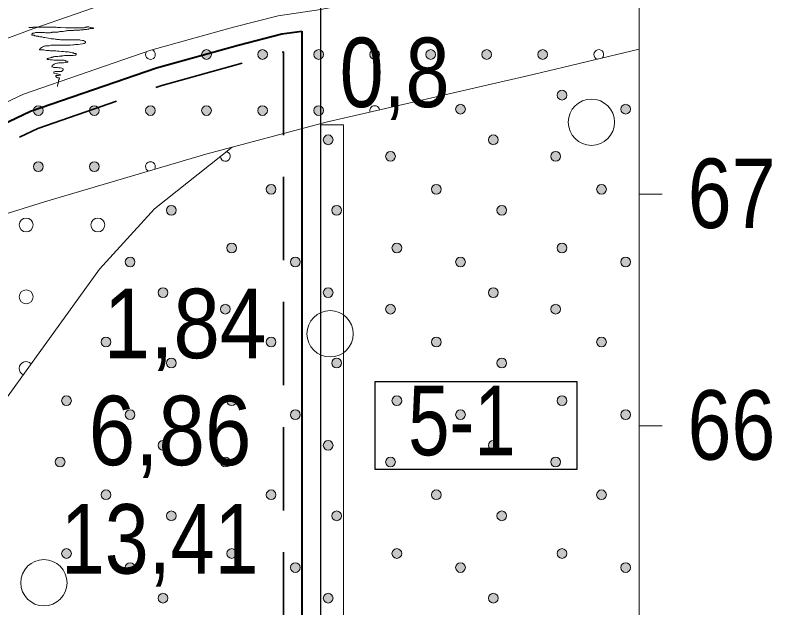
# Model space of a CAD drawing. Extents: x 640104 to 640970, y 6442278 to 6442689.
# Drawn here: x 640391.47 to 640424.15, y 6442590.14 to 6442615.73 of the extents above; entities that cross this region are included whole.
import ezdxf
from ezdxf.enums import TextEntityAlignment as Align

# ---------------------------------------------------------------- set-up
doc = ezdxf.new("R2010")
doc.units = 0
doc.header["$LTSCALE"] = 1.2
doc.linetypes.add('MEDIUM_DASHED', pattern=[4.5, 3, -1.5])
for name, color, linetype, lineweight in [('30', 7, 'Continuous', 13), ('31', 7, 'Continuous', 13), ('32', 7, 'Continuous', 25), ('33', 7, 'Continuous', 13), ('35', 7, 'Continuous', 35), ('40', 7, 'Continuous', 13), ('43', 7, 'Continuous', 13), ('44', 7, 'Continuous', 13), ('45', 7, 'Continuous', 13), ('47', 7, 'Continuous', 13)]:
    doc.layers.add(name, color=color, linetype=linetype, lineweight=lineweight)

msp = doc.modelspace()

# ---------------------------------------------------------------- hatches: boundary and pattern name
at = {"layer": '44'}
for points in [[(640415.301, 6442612.277, 1), (640414.881, 6442612.277, 1)], [(640410.916, 6442611.671, 1), (640410.496, 6442611.671, 1)], [(640418.049, 6442611.671, 1), (640417.629, 6442611.671, 1)], [(640405.202, 6442610.349, 1), (640404.782, 6442610.349, 1)], [(640412.335, 6442610.349, 1), (640411.915, 6442610.349, 1)], [(640407.894, 6442609.634, 1), (640407.474, 6442609.634, 1)], [(640415.027, 6442609.634, 1), (640414.607, 6442609.634, 1)], [(640402.739, 6442608.215, 1), (640402.319, 6442608.215, 1)], [(640409.872, 6442608.215, 1), (640409.452, 6442608.215, 1)], [(640417.005, 6442608.215, 1), (640416.585, 6442608.215, 1)], [(640398.433, 6442607.307, 1), (640398.013, 6442607.307, 1)], [(640405.566, 6442607.307, 1), (640405.146, 6442607.307, 1)], [(640412.699, 6442607.307, 1), (640412.279, 6442607.307, 1)], [(640401.035, 6442605.681, 1), (640400.615, 6442605.681, 1)], [(640408.168, 6442605.681, 1), (640407.748, 6442605.681, 1)], [(640415.301, 6442605.681, 1), (640414.881, 6442605.681, 1)], [(640396.65, 6442605.075, 1), (640396.23, 6442605.075, 1)], [(640403.783, 6442605.075, 1), (640403.363, 6442605.075, 1)], [(640410.916, 6442605.075, 1), (640410.496, 6442605.075, 1)], [(640418.049, 6442605.075, 1), (640417.629, 6442605.075, 1)], [(640398.069, 6442603.753, 1), (640397.649, 6442603.753, 1)], [(640405.202, 6442603.753, 1), (640404.782, 6442603.753, 1)], [(640412.335, 6442603.753, 1), (640411.915, 6442603.753, 1)], [(640400.761, 6442603.038, 1), (640400.341, 6442603.038, 1)], [(640407.894, 6442603.038, 1), (640407.474, 6442603.038, 1)], [(640415.027, 6442603.038, 1), (640414.607, 6442603.038, 1)], [(640395.606, 6442601.619, 1), (640395.186, 6442601.619, 1)], [(640402.739, 6442601.619, 1), (640402.319, 6442601.619, 1)], [(640409.872, 6442601.619, 1), (640409.452, 6442601.619, 1)], [(640417.005, 6442601.619, 1), (640416.585, 6442601.619, 1)], [(640398.433, 6442600.711, 1), (640398.013, 6442600.711, 1)], [(640405.566, 6442600.711, 1), (640405.146, 6442600.711, 1)], [(640412.699, 6442600.711, 1), (640412.279, 6442600.711, 1)], [(640393.902, 6442599.085, 1), (640393.482, 6442599.085, 1)], [(640401.035, 6442599.085, 1), (640400.615, 6442599.085, 1)], [(640408.168, 6442599.085, 1), (640407.748, 6442599.085, 1)], [(640415.301, 6442599.085, 1), (640414.881, 6442599.085, 1)], [(640396.65, 6442598.479, 1), (640396.23, 6442598.479, 1)], [(640403.783, 6442598.479, 1), (640403.363, 6442598.479, 1)], [(640410.916, 6442598.479, 1), (640410.496, 6442598.479, 1)], [(640418.049, 6442598.479, 1), (640417.629, 6442598.479, 1)], [(640398.069, 6442597.157, 1), (640397.649, 6442597.157, 1)], [(640405.202, 6442597.157, 1), (640404.782, 6442597.157, 1)], [(640412.335, 6442597.157, 1), (640411.915, 6442597.157, 1)], [(640393.628, 6442596.442, 1), (640393.208, 6442596.442, 1)], [(640400.761, 6442596.442, 1), (640400.341, 6442596.442, 1)], [(640407.894, 6442596.442, 1), (640407.474, 6442596.442, 1)], [(640415.027, 6442596.442, 1), (640414.607, 6442596.442, 1)], [(640395.606, 6442595.023, 1), (640395.186, 6442595.023, 1)], [(640402.739, 6442595.023, 1), (640402.319, 6442595.023, 1)], [(640409.872, 6442595.023, 1), (640409.452, 6442595.023, 1)], [(640417.005, 6442595.023, 1), (640416.585, 6442595.023, 1)], [(640398.433, 6442594.115, 1), (640398.013, 6442594.115, 1)], [(640405.566, 6442594.115, 1), (640405.146, 6442594.115, 1)], [(640412.699, 6442594.115, 1), (640412.279, 6442594.115, 1)], [(640393.902, 6442592.489, 1), (640393.482, 6442592.489, 1)], [(640401.035, 6442592.489, 1), (640400.615, 6442592.489, 1)], [(640408.168, 6442592.489, 1), (640407.748, 6442592.489, 1)], [(640415.301, 6442592.489, 1), (640414.881, 6442592.489, 1)], [(640396.65, 6442591.883, 1), (640396.23, 6442591.883, 1)], [(640403.783, 6442591.883, 1), (640403.363, 6442591.883, 1)], [(640410.916, 6442591.883, 1), (640410.496, 6442591.883, 1)], [(640418.049, 6442591.883, 1), (640417.629, 6442591.883, 1)], [(640398.069, 6442590.561, 1), (640397.649, 6442590.561, 1)], [(640405.202, 6442590.561, 1), (640404.782, 6442590.561, 1)], [(640412.335, 6442590.561, 1), (640411.915, 6442590.561, 1)]]:
    msp.add_hatch(color=256, dxfattribs=at).paths.add_polyline_path(points)
at = {"layer": '45'}
for points in [[(640399.948, 6442614.032, 1), (640399.528, 6442614.032, 1)], [(640402.368, 6442614.032, 1), (640401.948, 6442614.032, 1)], [(640404.788, 6442614.032, 1), (640404.368, 6442614.032, 1)], [(640407.208, 6442614.032, 1), (640406.788, 6442614.032, 1)], [(640409.628, 6442614.032, 1), (640409.208, 6442614.032, 1)], [(640412.048, 6442614.032, 1), (640411.628, 6442614.032, 1)], [(640414.468, 6442614.032, 1), (640414.048, 6442614.032, 1)], [(640392.688, 6442611.612, 1), (640392.268, 6442611.612, 1)], [(640395.108, 6442611.612, 1), (640394.688, 6442611.612, 1)], [(640397.528, 6442611.612, 1), (640397.108, 6442611.612, 1)], [(640399.948, 6442611.612, 1), (640399.528, 6442611.612, 1)], [(640402.368, 6442611.612, 1), (640401.948, 6442611.612, 1)], [(640404.788, 6442611.612, 1), (640404.368, 6442611.612, 1)], [(640392.688, 6442609.192, 1), (640392.268, 6442609.192, 1)], [(640395.108, 6442609.192, 1), (640394.688, 6442609.192, 1)]]:
    msp.add_hatch(color=256, dxfattribs=at).paths.add_polyline_path(points)

# ---------------------------------------------------------------- linework, layer by layer
at = {"layer": '30'}
for p, q in [((640418.42, 6442488), (640418.42, 6442668)), ((640418.42, 6442608), (640419.42, 6442608)), ((640418.42, 6442598), (640419.42, 6442598))]:
    msp.add_line(p, q, dxfattribs=at)
at = {"layer": '31'}
for points in [[(640357.94, 6442607.53), (640362.63, 6442607.41), (640367.38, 6442607.41), (640371.67, 6442607.59), (640374.36, 6442607.99), (640380.93, 6442610.64), (640387.33, 6442613.33), (640392.28, 6442615.15), (640398.1, 6442617.19), (640401.95, 6442618.28), (640404.86, 6442619.01), (640406.35, 6442619.17), (640407.57, 6442619.26), (640410.39, 6442619.66), (640412.14, 6442620.25), (640413.23, 6442621.05), (640415.56, 6442622.86), (640418.42, 6442625.44)], [(640350.61, 6442605.07), (640361.71, 6442604.69), (640369.18, 6442604.69), (640371.92, 6442604.84), (640374.62, 6442605.33), (640377.65, 6442606.24), (640381.25, 6442607.86), (640386.17, 6442609.64), (640391.84, 6442612.32), (640397.34, 6442614.22), (640400.9, 6442615.21), (640402.83, 6442615.7), (640404.68, 6442615.97), (640406.3, 6442616.29), (640409.23, 6442616.74), (640412.12, 6442617.42), (640413.87, 6442618.23), (640415.86, 6442619.53), (640418.42, 6442621.54)], [(640302.22, 6442612.41), (640318.66, 6442607.62), (640335.82, 6442604.24), (640359.18, 6442601.98), (640365.26, 6442601.88), (640371.15, 6442602.08), (640376.75, 6442602.96), (640387.02, 6442605.89), (640392.74, 6442607.67), (640399.71, 6442609.73), (640404.91, 6442611.11), (640413.85, 6442613.17), (640418.42, 6442614.26)], [(640283.68, 6442523.66), (640285.43, 6442524.03), (640297.52, 6442526.8), (640310.03, 6442531.34), (640323.29, 6442537.98), (640334.86, 6442544.42), (640343.76, 6442550.3), (640349.45, 6442554.85), (640357.08, 6442560.74), (640362.52, 6442565.74), (640369.51, 6442571.79), (640374.98, 6442577.56), (640379.02, 6442582.52), (640385.32, 6442590.78), (640390.41, 6442598.26), (640395.12, 6442604.77), (640397.49, 6442607.37), (640400.85, 6442610.03)]]:
    msp.add_lwpolyline(points, dxfattribs=at)
at = {"layer": '32'}
msp.add_line((640404.66, 6442618.96), (640404.66, 6442514), dxfattribs=at)
at = {"layer": '33'}
msp.add_lwpolyline([(640405.66, 6442589), (640405.66, 6442611), (640404.66, 6442611), (640404.66, 6442589)], close=True, dxfattribs=at)
at = {"layer": '33', "lineweight": 25}
msp.add_lwpolyline([(640407.02, 6442599.92), (640415.73, 6442599.92), (640415.73, 6442596.12), (640407.02, 6442596.12)], close=True, dxfattribs=at)
at = {"layer": '35', "lineweight": 40}
msp.add_line((640403.86, 6442615.04), (640403.86, 6442514.72), dxfattribs=at)
at = {"layer": '35', "linetype": 'MEDIUM_DASHED'}
msp.add_line((640403.06, 6442614.15), (640403.06, 6442553.81), dxfattribs=at)
at = {"layer": '35', "lineweight": 40}
msp.add_lwpolyline([(640350.56, 6442604.27), (640361.69, 6442603.89), (640369.2, 6442603.89), (640372.02, 6442604.05), (640374.81, 6442604.55), (640377.93, 6442605.49), (640381.55, 6442607.12), (640386.48, 6442608.9), (640392.14, 6442611.58), (640397.58, 6442613.45), (640401.1, 6442614.43), (640402.99, 6442614.92), (640403.86, 6442615.04)], dxfattribs=at)
at = {"layer": '35', "linetype": 'MEDIUM_DASHED'}
msp.add_lwpolyline([(640350.51, 6442603.47), (640361.68, 6442603.09), (640369.22, 6442603.09), (640372.11, 6442603.25), (640375, 6442603.77), (640378.21, 6442604.74), (640381.85, 6442606.38), (640386.78, 6442608.16), (640392.45, 6442610.84), (640397.81, 6442612.69), (640403.06, 6442614.15)], dxfattribs=at)
at = {"layer": '40'}
for points in [[(640392.06, 6442615.2), (640392.1, 6442615.2), (640392.17, 6442615.2), (640392.24, 6442615.2), (640392.26, 6442615.21), (640392.33, 6442615.21), (640392.43, 6442615.21), (640392.65, 6442615.21), (640392.77, 6442615.21), (640392.79, 6442615.21), (640392.82, 6442615.21), (640392.87, 6442615.21), (640392.92, 6442615.21), (640392.99, 6442615.21), (640393.05, 6442615.21), (640393.09, 6442615.21), (640393.15, 6442615.21), (640393.19, 6442615.21), (640393.24, 6442615.21), (640393.3, 6442615.2), (640393.33, 6442615.2), (640393.38, 6442615.2), (640393.44, 6442615.2), (640393.67, 6442615.19), (640393.87, 6442615.19), (640393.94, 6442615.19), (640393.98, 6442615.19), (640394, 6442615.19), (640394.03, 6442615.19), (640394.08, 6442615.19), (640394.15, 6442615.19), (640394.18, 6442615.19), (640394.2, 6442615.19), (640394.22, 6442615.19), (640394.24, 6442615.19), (640394.29, 6442615.19), (640394.31, 6442615.19), (640394.35, 6442615.19), (640394.41, 6442615.19), (640394.45, 6442615.19), (640394.5, 6442615.2), (640394.52, 6442615.21), (640394.57, 6442615.21), (640394.59, 6442615.22), (640394.63, 6442615.22), (640394.66, 6442615.22), (640394.68, 6442615.21), (640394.71, 6442615.2), (640394.74, 6442615.19), (640394.76, 6442615.19)], [(640393.08, 6442614.99), (640393.06, 6442614.98), (640393.02, 6442614.98), (640392.99, 6442614.97), (640392.97, 6442614.97), (640392.95, 6442614.97), (640392.91, 6442614.97), (640392.88, 6442614.97), (640392.85, 6442614.97), (640392.8, 6442614.97), (640392.78, 6442614.97), (640392.74, 6442614.98), (640392.71, 6442614.98), (640392.69, 6442614.98), (640392.67, 6442614.98), (640392.63, 6442614.98), (640392.6, 6442614.98), (640392.55, 6442614.98), (640392.53, 6442614.98), (640392.51, 6442614.98), (640392.47, 6442614.98), (640392.44, 6442614.98), (640392.41, 6442614.98), (640392.39, 6442614.98), (640392.35, 6442614.98), (640392.32, 6442614.97), (640392.3, 6442614.95), (640392.27, 6442614.95), (640392.24, 6442614.95), (640392.23, 6442614.94), (640392.21, 6442614.93), (640392.19, 6442614.91), (640392.19, 6442614.89), (640392.19, 6442614.87), (640392.26, 6442614.86), (640392.3, 6442614.86), (640392.32, 6442614.84), (640392.35, 6442614.84), (640392.38, 6442614.83), (640392.39, 6442614.83), (640392.43, 6442614.83), (640392.47, 6442614.82), (640392.49, 6442614.81), (640392.54, 6442614.79), (640392.59, 6442614.79), (640392.63, 6442614.79), (640392.67, 6442614.78), (640392.7, 6442614.77), (640392.75, 6442614.76), (640392.83, 6442614.75)], [(640394.76, 6442615.19), (640394.79, 6442615.19), (640394.82, 6442615.19), (640394.85, 6442615.19), (640394.87, 6442615.17), (640394.85, 6442615.16), (640394.86, 6442615.17), (640394.83, 6442615.16), (640394.8, 6442615.15), (640394.76, 6442615.15), (640394.74, 6442615.15), (640394.71, 6442615.15), (640394.68, 6442615.14), (640394.66, 6442615.14), (640394.64, 6442615.12), (640394.6, 6442615.12), (640394.55, 6442615.11), (640394.53, 6442615.11), (640394.45, 6442615.11), (640394.42, 6442615.1), (640394.39, 6442615.1), (640394.36, 6442615.09), (640394.33, 6442615.09), (640394.31, 6442615.09), (640394.27, 6442615.08), (640394.24, 6442615.08), (640394.17, 6442615.08), (640394.13, 6442615.08), (640394.08, 6442615.08), (640394.03, 6442615.08), (640393.99, 6442615.07), (640393.95, 6442615.07), (640393.91, 6442615.07), (640393.87, 6442615.07), (640393.76, 6442615.07), (640393.74, 6442615.07), (640393.71, 6442615.06), (640393.67, 6442615.05), (640393.6, 6442615.04), (640393.55, 6442615.03), (640393.51, 6442615.03), (640393.45, 6442615.03), (640393.41, 6442615.03), (640393.38, 6442615.01), (640393.34, 6442615.01), (640393.32, 6442615), (640393.3, 6442615), (640393.26, 6442615), (640393.23, 6442614.99), (640393.2, 6442614.99), (640393.11, 6442614.99), (640393.08, 6442614.99)], [(640392.83, 6442614.75), (640392.92, 6442614.74), (640392.99, 6442614.72), (640393.03, 6442614.71), (640393.09, 6442614.71), (640393.15, 6442614.71), (640393.2, 6442614.7), (640393.24, 6442614.7), (640393.27, 6442614.68), (640393.33, 6442614.68), (640393.37, 6442614.68), (640393.43, 6442614.67), (640393.48, 6442614.67), (640393.53, 6442614.67), (640393.59, 6442614.67), (640393.65, 6442614.67), (640393.69, 6442614.67), (640393.71, 6442614.67), (640393.76, 6442614.67), (640393.81, 6442614.67), (640393.87, 6442614.67), (640393.93, 6442614.67), (640393.99, 6442614.67), (640394.03, 6442614.67), (640394.08, 6442614.67), (640394.11, 6442614.67), (640394.15, 6442614.67), (640394.19, 6442614.67), (640394.23, 6442614.66), (640394.27, 6442614.66), (640394.3, 6442614.65), (640394.39, 6442614.64), (640394.43, 6442614.63), (640394.47, 6442614.61), (640394.5, 6442614.6), (640394.52, 6442614.59), (640394.52, 6442614.57), (640394.51, 6442614.55), (640394.5, 6442614.54), (640394.48, 6442614.53), (640394.47, 6442614.51), (640394.43, 6442614.51), (640394.38, 6442614.49), (640394.28, 6442614.48), (640394.19, 6442614.47), (640394.15, 6442614.46), (640394.08, 6442614.46), (640394.03, 6442614.45), (640393.96, 6442614.45), (640393.87, 6442614.44), (640393.75, 6442614.44), (640393.63, 6442614.44)], [(640393.63, 6442614.44), (640393.58, 6442614.44), (640393.53, 6442614.44), (640393.47, 6442614.44), (640393.43, 6442614.44), (640393.39, 6442614.44), (640393.34, 6442614.44), (640393.28, 6442614.43), (640393.16, 6442614.43), (640393.11, 6442614.43), (640393.07, 6442614.43), (640393.02, 6442614.43), (640392.94, 6442614.41), (640392.85, 6442614.41), (640392.82, 6442614.4), (640392.78, 6442614.4), (640392.76, 6442614.39), (640392.74, 6442614.39), (640392.71, 6442614.39), (640392.69, 6442614.38), (640392.67, 6442614.37), (640392.65, 6442614.35), (640392.61, 6442614.33), (640392.59, 6442614.31), (640392.58, 6442614.3), (640392.55, 6442614.29), (640392.55, 6442614.27), (640392.53, 6442614.26), (640392.52, 6442614.24), (640392.54, 6442614.23), (640392.56, 6442614.23), (640392.6, 6442614.23), (640392.63, 6442614.23), (640392.71, 6442614.23), (640392.76, 6442614.22), (640392.83, 6442614.21), (640392.91, 6442614.2), (640392.95, 6442614.2), (640392.99, 6442614.19), (640393.03, 6442614.19), (640393.14, 6442614.19), (640393.23, 6442614.19), (640393.3, 6442614.18), (640393.37, 6442614.17), (640393.47, 6442614.16), (640393.56, 6442614.16), (640393.64, 6442614.14), (640393.7, 6442614.14), (640393.76, 6442614.14), (640393.82, 6442614.13)], [(640393.82, 6442614.13), (640393.85, 6442614.13), (640393.88, 6442614.12), (640393.94, 6442614.11), (640393.99, 6442614.1), (640394.02, 6442614.08), (640394.05, 6442614.07), (640394.09, 6442614.07), (640394.11, 6442614.06), (640394.11, 6442614.03), (640394.1, 6442614.02), (640394.08, 6442614.01), (640394.06, 6442614), (640393.98, 6442613.99), (640393.94, 6442613.99), (640393.91, 6442613.99), (640393.87, 6442613.99), (640393.81, 6442613.99), (640393.75, 6442613.99), (640393.72, 6442613.99), (640393.69, 6442613.99), (640393.6, 6442613.99), (640393.55, 6442613.97), (640393.53, 6442613.97), (640393.49, 6442613.97), (640393.47, 6442613.96), (640393.43, 6442613.96), (640393.37, 6442613.96), (640393.32, 6442613.95), (640393.27, 6442613.95), (640393.23, 6442613.94), (640393.2, 6442613.94), (640393.17, 6442613.94), (640393.15, 6442613.93), (640393.11, 6442613.93), (640393.1, 6442613.91), (640393.06, 6442613.91), (640393.04, 6442613.9), (640393.02, 6442613.9), (640392.99, 6442613.89), (640392.95, 6442613.88), (640392.91, 6442613.87), (640392.87, 6442613.86), (640392.86, 6442613.84), (640392.86, 6442613.81), (640392.88, 6442613.81), (640392.93, 6442613.81), (640392.99, 6442613.8), (640393.05, 6442613.8), (640393.08, 6442613.8), (640393.15, 6442613.79), (640393.19, 6442613.79)], [(640393.19, 6442613.79), (640393.2, 6442613.79), (640393.23, 6442613.79), (640393.27, 6442613.79), (640393.31, 6442613.79), (640393.34, 6442613.79), (640393.41, 6442613.78), (640393.47, 6442613.78), (640393.49, 6442613.78), (640393.52, 6442613.78), (640393.55, 6442613.78), (640393.59, 6442613.78), (640393.63, 6442613.77), (640393.66, 6442613.75), (640393.69, 6442613.75), (640393.72, 6442613.74), (640393.75, 6442613.73), (640393.75, 6442613.7), (640393.67, 6442613.68), (640393.56, 6442613.67), (640393.52, 6442613.67), (640393.45, 6442613.67), (640393.41, 6442613.67), (640393.36, 6442613.67), (640393.31, 6442613.66), (640393.27, 6442613.66), (640393.22, 6442613.64), (640393.16, 6442613.62), (640393.15, 6442613.6), (640393.11, 6442613.59), (640393.1, 6442613.57), (640393.08, 6442613.55), (640393.07, 6442613.53), (640393.06, 6442613.51), (640393.07, 6442613.5), (640393.11, 6442613.49), (640393.15, 6442613.47), (640393.24, 6442613.47), (640393.31, 6442613.47), (640393.35, 6442613.46), (640393.39, 6442613.45), (640393.43, 6442613.45), (640393.49, 6442613.44), (640393.55, 6442613.42), (640393.55, 6442613.39), (640393.55, 6442613.36), (640393.54, 6442613.35), (640393.49, 6442613.31), (640393.47, 6442613.3), (640393.43, 6442613.3), (640393.37, 6442613.3), (640393.31, 6442613.3), (640393.27, 6442613.3), (640393.21, 6442613.3), (640393.15, 6442613.28), (640393.15, 6442613.26), (640393.14, 6442613.24), (640393.15, 6442613.23), (640393.17, 6442613.22), (640393.25, 6442613.19), (640393.31, 6442613.19), (640393.34, 6442613.18), (640393.38, 6442613.17), (640393.42, 6442613.16), (640393.44, 6442613.15), (640393.43, 6442613.14), (640393.39, 6442613.14), (640393.34, 6442613.13), (640393.27, 6442613.12), (640393.25, 6442613.12), (640393.23, 6442613.11), (640393.23, 6442613.08), (640393.24, 6442613.07), (640393.26, 6442613.06), (640393.28, 6442613.04), (640393.31, 6442613.03), (640393.35, 6442613.03), (640393.39, 6442613.02), (640393.39, 6442612.99), (640393.38, 6442612.97), (640393.37, 6442612.95), (640393.35, 6442612.92), (640393.34, 6442612.91), (640393.34, 6442612.87), (640393.34, 6442612.84), (640393.34, 6442612.82), (640393.33, 6442612.79), (640393.33, 6442612.76), (640393.32, 6442612.75), (640393.31, 6442612.71), (640393.31, 6442612.69), (640393.31, 6442612.66), (640393.31, 6442612.65), (640393.31, 6442612.67)]]:
    msp.add_lwpolyline(points, dxfattribs=at)
at = {"layer": '43'}
for centre in [(640391.949, 6442606.673), (640395.049, 6442606.673), (640391.949, 6442603.573)]:
    msp.add_circle(centre, 0.3, dxfattribs=at)
msp.add_arc((640391.949, 6442600.473), 0.3, 44.4665, 243.7619, dxfattribs=at)
at = {"layer": '44'}
for centre in [(640415.091, 6442612.277), (640410.706, 6442611.671), (640417.839, 6442611.671), (640404.992, 6442610.349), (640412.125, 6442610.349), (640407.684, 6442609.634), (640414.817, 6442609.634), (640402.529, 6442608.215), (640409.662, 6442608.215), (640416.795, 6442608.215), (640398.223, 6442607.307), (640405.356, 6442607.307), (640412.489, 6442607.307), (640400.825, 6442605.681), (640407.958, 6442605.681), (640415.091, 6442605.681), (640396.44, 6442605.075), (640403.573, 6442605.075), (640410.706, 6442605.075), (640417.839, 6442605.075), (640397.859, 6442603.753), (640404.992, 6442603.753), (640412.125, 6442603.753), (640400.551, 6442603.038), (640407.684, 6442603.038), (640414.817, 6442603.038), (640395.396, 6442601.619), (640402.529, 6442601.619), (640409.662, 6442601.619), (640416.795, 6442601.619), (640398.223, 6442600.711), (640405.356, 6442600.711), (640412.489, 6442600.711), (640393.692, 6442599.085), (640400.825, 6442599.085), (640407.958, 6442599.085), (640415.091, 6442599.085), (640396.44, 6442598.479), (640403.573, 6442598.479), (640410.706, 6442598.479), (640417.839, 6442598.479), (640397.859, 6442597.157), (640404.992, 6442597.157), (640412.125, 6442597.157), (640393.418, 6442596.442), (640400.551, 6442596.442), (640407.684, 6442596.442), (640414.817, 6442596.442), (640395.396, 6442595.023), (640402.529, 6442595.023), (640409.662, 6442595.023), (640416.795, 6442595.023), (640398.223, 6442594.115), (640405.356, 6442594.115), (640412.489, 6442594.115), (640393.692, 6442592.489), (640400.825, 6442592.489), (640407.958, 6442592.489), (640415.091, 6442592.489), (640396.44, 6442591.883), (640403.573, 6442591.883), (640410.706, 6442591.883), (640417.839, 6442591.883), (640397.859, 6442590.561), (640404.992, 6442590.561), (640412.125, 6442590.561)]:
    msp.add_circle(centre, 0.21, dxfattribs=at)
msp.add_arc((640400.551, 6442609.634), 0.21, 180.1849, 76.6054, dxfattribs=at)
at = {"layer": '45'}
for centre in [(640399.738, 6442614.032), (640402.158, 6442614.032), (640404.578, 6442614.032), (640406.998, 6442614.032), (640409.418, 6442614.032), (640411.838, 6442614.032), (640414.258, 6442614.032), (640392.478, 6442611.612), (640394.898, 6442611.612), (640397.318, 6442611.612), (640399.738, 6442611.612), (640402.158, 6442611.612), (640404.578, 6442611.612), (640392.478, 6442609.192), (640394.898, 6442609.192)]:
    msp.add_circle(centre, 0.21, dxfattribs=at)
for centre, start, end in [((640397.318, 6442614.032), 146.0962, 70.4844), ((640416.678, 6442614.032), 313.6083, 253.2694), ((640406.998, 6442611.612), 6.684, 199.3052), ((640397.318, 6442609.192), 326.8692, 246.0846)]:
    msp.add_arc(centre, 0.21, start, end, dxfattribs=at)
at = {"layer": '47'}
for centre in [(640416.358, 6442611.106), (640405.076, 6442601.973), (640392.719, 6442591.228)]:
    msp.add_circle(centre, 1, dxfattribs=at)

# ---------------------------------------------------------------- texts
at = {"layer": '31', "width": 0.85}
for s, p in [('67', (640422.415, 6442606.54)), ('66', (640422.405, 6442596.54))]:
    msp.add_text(s, height=3, dxfattribs=at).set_placement(p, align=Align.CENTER)
at = {"layer": '32', "width": 0.85}
msp.add_text('0,8', height=3, dxfattribs=at).set_placement((640407.86, 6442611.76), align=Align.CENTER)
at = {"layer": '33'}
for s, width, p in [('1,84', 0.9, (640398.81, 6442600.92)), ('5-1', 0.8, (640410.765, 6442596.73)), ('6,86', 0.9, (640398.165, 6442596.3)), ('13,41', 0.85, (640397.715, 6442591.62))]:
    msp.add_text(s, height=3, dxfattribs=dict(at, width=width)).set_placement(p, align=Align.CENTER)

doc.saveas('drawing.dxf')
